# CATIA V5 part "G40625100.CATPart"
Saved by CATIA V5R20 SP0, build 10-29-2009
Part number: G40625100
Revision: 5
Definition: design
Nomenclature: G40625100
Source: made
Description: NOT SPECIFIED
Bounding box of the stored display mesh (mm): x -50 to 50, y -10 to 10, z -25 to 0
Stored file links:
  C:\Users\Raffaele\Desktop\3D X SITO CF\BOLEX\30-GUIDE STRIP REF 406\G40625100.CATPart
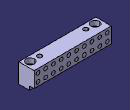
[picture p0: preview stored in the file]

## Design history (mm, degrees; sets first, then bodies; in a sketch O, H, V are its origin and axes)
Body1 "MANIFOLD_SOLID_BREP #3688" (main body)
  Solid1: solid without history
Body2 "MANIFOLD_SOLID_BREP #3826"
  Solid2: solid without history
Body3 "MANIFOLD_SOLID_BREP #3964"
  Solid3: solid without history
Body4 "MANIFOLD_SOLID_BREP #4102"
  Solid4: solid without history
Body5 "MANIFOLD_SOLID_BREP #4240"
  Solid5: solid without history
Body6 "MANIFOLD_SOLID_BREP #4378"
  Solid6: solid without history
Body7 "MANIFOLD_SOLID_BREP #4490"
  Solid7: solid without history
Body8 "MANIFOLD_SOLID_BREP #4602"
  Solid8: solid without history
Body9 "MANIFOLD_SOLID_BREP #4714"
  Solid9: solid without history
Body10 "MANIFOLD_SOLID_BREP #4826"
  Solid10: solid without history
Body11 "MANIFOLD_SOLID_BREP #4938"
  Solid11: solid without history
Body12 "MANIFOLD_SOLID_BREP #5050"
  Solid12: solid without history
Body13 "MANIFOLD_SOLID_BREP #5188"
  Solid13: solid without history
Body14 "MANIFOLD_SOLID_BREP #5326"
  Solid14: solid without history
Body15 "MANIFOLD_SOLID_BREP #5438"
  Solid15: solid without history
Body16 "MANIFOLD_SOLID_BREP #5550"
  Solid16: solid without history
Body17 "MANIFOLD_SOLID_BREP #5662"
  Solid17: solid without history
Body18 "MANIFOLD_SOLID_BREP #5774"
  Solid18: solid without history
Body19 "MANIFOLD_SOLID_BREP #5886"
  Solid19: solid without history
Body20 "MANIFOLD_SOLID_BREP #5998"
  Solid20: solid without history
Body21 "MANIFOLD_SOLID_BREP #6110"
  Solid21: solid without history
Body22 "MANIFOLD_SOLID_BREP #6222"
  Solid22: solid without history
Body23 "MANIFOLD_SOLID_BREP #6334"
  Solid23: solid without history
Body24 "MANIFOLD_SOLID_BREP #6446"
  Solid24: solid without history
Body25 "MANIFOLD_SOLID_BREP #6584"
  Solid25: solid without history
Body26 "MANIFOLD_SOLID_BREP #6722"
  Solid26: solid without history
Body27 "MANIFOLD_SOLID_BREP #6834"
  Solid27: solid without history
Body28 "MANIFOLD_SOLID_BREP #6946"
  Solid28: solid without history
Body29 "MANIFOLD_SOLID_BREP #7058"
  Solid29: solid without history
Body30 "MANIFOLD_SOLID_BREP #7170"
  Solid30: solid without history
